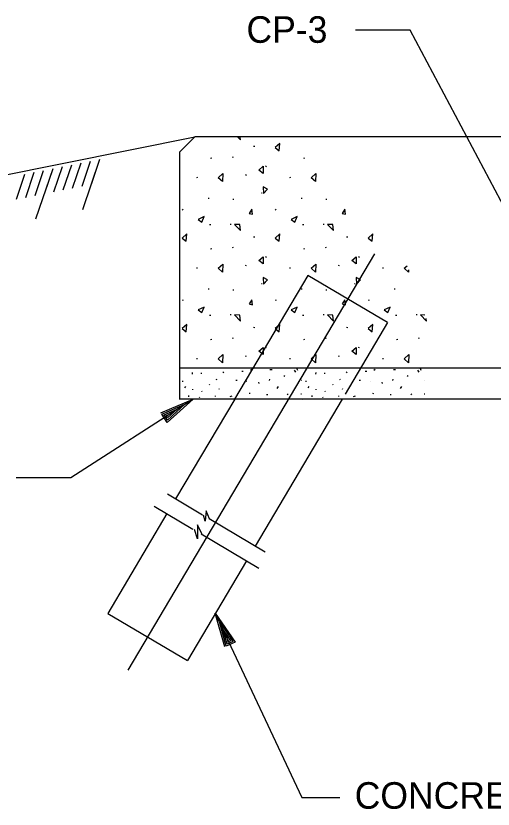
# Model space of a CAD drawing. Extents: x 44742.55 to 44745.38, y 44738.95 to 44741.13.
# Drawn here: x 44742.882 to 44743.044, y 44740.239 to 44740.5083 of the extents above; entities that cross this region are included whole.
import ezdxf

# ---------------------------------------------------------------- set-up
doc = ezdxf.new("R2010")
doc.units = 0
for name, color, linetype in [('G-ANNO-PATT', 7, 'Continuous'), ('Level 1', 7, 'Continuous'), ('Level 10', 7, 'Continuous'), ('Level 2', 7, 'Continuous'), ('Level 3', 7, 'Continuous'), ('Level 4', 7, 'Continuous'), ('S-ANNO-DIMS', 7, 'Continuous')]:
    doc.layers.add(name, color=color, linetype=linetype)

msp = doc.modelspace()

# ---------------------------------------------------------------- linework, layer by layer
at = {"layer": 'G-ANNO-PATT'}
for p, q in [((44742.96305, 44740.46391), (44742.96264, 44740.46398)), ((44742.94843, 44740.45995), (44742.94801, 44740.45984)), ((44742.95571, 44740.46037), (44742.95541, 44740.46026)), ((44742.97999, 44740.45995), (44742.97957, 44740.45984)), ((44742.96702, 44740.45706), (44742.96667, 44740.45727)), ((44742.94365, 44740.45341), (44742.94331, 44740.45337)), ((44742.96022, 44740.45416), (44742.95988, 44740.45431)), ((44742.97521, 44740.45341), (44742.97487, 44740.45337)), ((44742.96562, 44740.44809), (44742.96531, 44740.44811)), ((44742.9476, 44740.44626), (44742.94728, 44740.44631)), ((44742.956, 44740.44599), (44742.95558, 44740.44599)), ((44742.97916, 44740.44626), (44742.97885, 44740.44631)), ((44742.98756, 44740.44599), (44742.98714, 44740.44599)), ((44742.93875, 44740.44258), (44742.93838, 44740.44239)), ((44742.97031, 44740.44258), (44742.96994, 44740.44239)), ((44742.9481, 44740.43739), (44742.94767, 44740.43739)), ((44742.9551, 44740.43754), (44742.9547, 44740.43754)), ((44742.97966, 44740.43739), (44742.97924, 44740.43739)), ((44742.98666, 44740.43754), (44742.98626, 44740.43754)), ((44742.96305, 44740.43317), (44742.96264, 44740.43324)), ((44742.99461, 44740.43317), (44742.9942, 44740.43324)), ((44742.94843, 44740.42921), (44742.94801, 44740.42909)), ((44742.95571, 44740.42963), (44742.95541, 44740.42952)), ((44742.97999, 44740.42921), (44742.97957, 44740.42909)), ((44742.98727, 44740.42963), (44742.98697, 44740.42952)), ((44742.96702, 44740.42632), (44742.96667, 44740.42653)), ((44742.99859, 44740.42632), (44742.99824, 44740.42653)), ((44742.96022, 44740.42341), (44742.95988, 44740.42357)), ((44742.99178, 44740.42341), (44742.99145, 44740.42357)), ((44742.94365, 44740.42266), (44742.94331, 44740.42263)), ((44742.97521, 44740.42266), (44742.97487, 44740.42263)), ((44743.00677, 44740.42266), (44743.00643, 44740.42263)), ((44742.96562, 44740.41734), (44742.96531, 44740.41737)), ((44742.99718, 44740.41734), (44742.99687, 44740.41737)), ((44742.9476, 44740.41552), (44742.94728, 44740.41557)), ((44742.956, 44740.41525), (44742.95558, 44740.41525)), ((44742.97916, 44740.41552), (44742.97885, 44740.41557)), ((44742.98756, 44740.41525), (44742.98714, 44740.41525)), ((44743.01072, 44740.41552), (44743.01041, 44740.41557)), ((44742.93875, 44740.41184), (44742.93838, 44740.41165)), ((44742.97031, 44740.41184), (44742.96994, 44740.41165)), ((44743.00188, 44740.41184), (44743.0015, 44740.41165)), ((44742.9481, 44740.40665), (44742.94767, 44740.40665)), ((44742.9551, 44740.4068), (44742.9547, 44740.4068)), ((44742.97966, 44740.40665), (44742.97924, 44740.40665)), ((44742.98666, 44740.4068), (44742.98626, 44740.4068)), ((44743.01122, 44740.40665), (44743.0108, 44740.40665)), ((44743.01822, 44740.4068), (44743.01782, 44740.4068)), ((44742.96305, 44740.40243), (44742.96264, 44740.4025)), ((44742.99461, 44740.40243), (44742.9942, 44740.4025)), ((44742.94843, 44740.39847), (44742.94801, 44740.39835)), ((44742.95571, 44740.39889), (44742.95541, 44740.39877)), ((44742.97999, 44740.39847), (44742.97957, 44740.39835)), ((44742.98727, 44740.39889), (44742.98697, 44740.39877)), ((44743.01156, 44740.39847), (44743.01113, 44740.39835)), ((44743.01884, 44740.39889), (44743.01853, 44740.39877)), ((44742.96702, 44740.39558), (44742.96667, 44740.39579)), ((44742.99859, 44740.39558), (44742.99824, 44740.39579)), ((44742.94365, 44740.39192), (44742.94331, 44740.39189)), ((44742.96022, 44740.39267), (44742.95988, 44740.39283)), ((44742.97521, 44740.39192), (44742.97487, 44740.39189)), ((44742.99178, 44740.39267), (44742.99145, 44740.39283)), ((44743.00677, 44740.39192), (44743.00643, 44740.39189)), ((44742.96159, 44740.38803), (44742.96202, 44740.38837)), ((44742.96822, 44740.3883), (44742.96891, 44740.38831)), ((44742.97702, 44740.38731), (44742.97651, 44740.38805)), ((44742.97725, 44740.38871), (44742.97756, 44740.38803)), ((44743.00345, 44740.38803), (44743.00389, 44740.38837)), ((44743.0101, 44740.3883), (44743.01078, 44740.38831)), ((44742.94185, 44740.3872), (44742.94177, 44740.38671)), ((44742.94501, 44740.38674), (44742.94497, 44740.38718)), ((44742.95001, 44740.3849), (44742.95032, 44740.38499)), ((44742.95252, 44740.38711), (44742.95224, 44740.38752)), ((44742.95917, 44740.38756), (44742.95864, 44740.38764)), ((44742.96803, 44740.38499), (44742.96793, 44740.38449)), ((44742.97299, 44740.38587), (44742.97325, 44740.3862)), ((44742.98373, 44740.3872), (44742.98363, 44740.38671)), ((44742.98688, 44740.38674), (44742.98684, 44740.38718)), ((44742.99188, 44740.3849), (44742.9922, 44740.38499)), ((44742.9944, 44740.38711), (44742.99411, 44740.38752)), ((44743.00104, 44740.38756), (44743.00052, 44740.38764)), ((44743.00991, 44740.38499), (44743.00981, 44740.38449)), ((44743.01486, 44740.38587), (44743.01513, 44740.3862)), ((44742.93867, 44740.38405), (44742.93864, 44740.38446)), ((44742.93931, 44740.38202), (44742.93963, 44740.38251)), ((44742.9478, 44740.38293), (44742.9477, 44740.38315)), ((44742.95665, 44740.38462), (44742.95704, 44740.38462)), ((44742.96039, 44740.38415), (44742.96029, 44740.38423)), ((44742.96454, 44740.38352), (44742.96441, 44740.38396)), ((44742.97066, 44740.38187), (44742.97112, 44740.38247)), ((44742.97885, 44740.38465), (44742.97889, 44740.3846)), ((44742.98054, 44740.38405), (44742.98052, 44740.38446)), ((44742.98117, 44740.38202), (44742.9815, 44740.38251)), ((44742.98967, 44740.38293), (44742.98958, 44740.38315)), ((44742.99852, 44740.38462), (44742.99892, 44740.38462)), ((44743.00227, 44740.38415), (44743.00217, 44740.38423)), ((44743.00642, 44740.38352), (44743.00628, 44740.38396)), ((44743.01253, 44740.38187), (44743.01299, 44740.38247)), ((44743.02073, 44740.38465), (44743.02077, 44740.3846)), ((44742.94198, 44740.38137), (44742.94201, 44740.38155)), ((44742.94515, 44740.38063), (44742.9451, 44740.38096)), ((44742.95098, 44740.38157), (44742.95106, 44740.38179)), ((44742.9614, 44740.37998), (44742.96142, 44740.38038)), ((44742.96709, 44740.37973), (44742.9675, 44740.37974)), ((44742.9741, 44740.37963), (44742.97443, 44740.38002)), ((44742.97888, 44740.37988), (44742.97869, 44740.37984)), ((44742.98385, 44740.38137), (44742.98388, 44740.38155)), ((44742.98702, 44740.38063), (44742.98698, 44740.38096)), ((44742.99285, 44740.38157), (44742.99293, 44740.38179)), ((44743.00327, 44740.37998), (44743.0033, 44740.38038)), ((44743.00896, 44740.37973), (44743.00938, 44740.37974)), ((44743.01597, 44740.37963), (44743.01631, 44740.38002)), ((44743.02076, 44740.37988), (44743.02056, 44740.37984)), ((44742.93755, 44740.37824), (44742.93796, 44740.37827)), ((44742.94069, 44740.37902), (44742.94068, 44740.37948)), ((44742.94438, 44740.37862), (44742.9443, 44740.37886)), ((44742.94975, 44740.37914), (44742.94973, 44740.37936)), ((44742.95474, 44740.3791), (44742.95538, 44740.37933)), ((44742.97942, 44740.37824), (44742.97984, 44740.37827)), ((44742.98256, 44740.37902), (44742.98256, 44740.37948)), ((44742.98626, 44740.37862), (44742.98617, 44740.37886)), ((44742.99163, 44740.37914), (44742.9916, 44740.37936)), ((44742.9966, 44740.3791), (44742.99726, 44740.37933))]:
    msp.add_line(p, q, dxfattribs=at)
for points in [[(44742.95726, 44740.46714), (44742.95818, 44740.4662), (44742.95811, 44740.46714)], [(44743.01522, 44740.42129), (44743.01377, 44740.42262), (44743.01473, 44740.42348)], [(44743.01527, 44740.42205), (44743.01522, 44740.42129)], [(44743.02081, 44740.40671), (44743.01927, 44740.4068), (44743.02131, 44740.40472), (44743.02124, 44740.40555)]]:
    msp.add_lwpolyline(points, dxfattribs=at)
for points in [[(44742.97158, 44740.46504), (44742.96998, 44740.46364), (44742.97131, 44740.46252)], [(44742.96592, 44740.45485), (44742.96442, 44740.45598), (44742.96585, 44740.45726)], [(44742.9521, 44740.45203), (44742.95065, 44740.45337), (44742.95225, 44740.4548)], [(44742.98366, 44740.45203), (44742.98221, 44740.45337), (44742.98381, 44740.4548)], [(44742.96607, 44740.44798), (44742.96741, 44740.44948), (44742.96592, 44740.45027)], [(44742.96231, 44740.44099), (44742.9621, 44740.4427), (44742.96113, 44740.44127)], [(44742.99388, 44740.44099), (44742.99366, 44740.4427), (44742.9927, 44740.44127)], [(44742.94514, 44740.4383), (44742.94588, 44740.44022), (44742.94381, 44740.43921)], [(44742.9767, 44740.4383), (44742.97745, 44740.44022), (44742.97538, 44740.43921)], [(44742.95802, 44740.43744), (44742.95615, 44740.43754), (44742.95818, 44740.43546)], [(44742.98959, 44740.43744), (44742.98771, 44740.43754), (44742.98974, 44740.43546)], [(44742.94002, 44740.4343), (44742.93842, 44740.4329), (44742.93974, 44740.43178)], [(44742.97158, 44740.4343), (44742.96998, 44740.4329), (44742.97131, 44740.43178)], [(44743.00314, 44740.4343), (44743.00154, 44740.4329), (44743.00287, 44740.43178)], [(44742.96592, 44740.42411), (44742.96442, 44740.42524), (44742.96585, 44740.42652)], [(44742.99748, 44740.42411), (44742.99598, 44740.42524), (44742.99742, 44740.42652)], [(44742.9521, 44740.42129), (44742.95065, 44740.42262), (44742.95225, 44740.42405)], [(44742.98366, 44740.42129), (44742.98221, 44740.42262), (44742.98381, 44740.42405)], [(44742.96607, 44740.41723), (44742.96741, 44740.41873), (44742.96592, 44740.41953)], [(44742.99763, 44740.41723), (44742.99897, 44740.41873), (44742.99748, 44740.41953)], [(44742.96231, 44740.41025), (44742.9621, 44740.41196), (44742.96113, 44740.41053)], [(44742.99388, 44740.41025), (44742.99366, 44740.41196), (44742.9927, 44740.41053)], [(44742.94514, 44740.40756), (44742.94588, 44740.40948), (44742.94381, 44740.40847)], [(44742.9767, 44740.40756), (44742.97745, 44740.40948), (44742.97538, 44740.40847)], [(44743.00827, 44740.40756), (44743.00901, 44740.40948), (44743.00694, 44740.40847)], [(44742.95802, 44740.40669), (44742.95615, 44740.4068), (44742.95818, 44740.40472)], [(44742.98959, 44740.40669), (44742.98771, 44740.4068), (44742.98974, 44740.40472)], [(44742.94002, 44740.40355), (44742.93842, 44740.40216), (44742.93974, 44740.40104)], [(44742.97158, 44740.40355), (44742.96998, 44740.40216), (44742.97131, 44740.40104)], [(44743.00314, 44740.40355), (44743.00154, 44740.40216), (44743.00287, 44740.40104)], [(44742.96592, 44740.39337), (44742.96442, 44740.3945), (44742.96585, 44740.39577)], [(44742.99748, 44740.39337), (44742.99598, 44740.3945), (44742.99742, 44740.39577)], [(44742.9521, 44740.39055), (44742.95065, 44740.39188), (44742.95225, 44740.39331)], [(44742.98366, 44740.39055), (44742.98221, 44740.39188), (44742.98381, 44740.39331)], [(44743.01522, 44740.39055), (44743.01377, 44740.39188), (44743.01538, 44740.39331)]]:
    msp.add_lwpolyline(points, close=True, dxfattribs=at)
at = {"layer": 'Level 1'}
for p, q in [((44742.89807, 44740.44923), (44742.90096, 44740.45777)), ((44742.90125, 44740.44986), (44742.90414, 44740.45841)), ((44742.90444, 44740.4505), (44742.90733, 44740.45904)), ((44742.90473, 44740.44259), (44742.91052, 44740.45968)), ((44742.90763, 44740.45113), (44742.91052, 44740.45968)), ((44742.88532, 44740.44668), (44742.88821, 44740.45522)), ((44742.88851, 44740.44731), (44742.8914, 44740.45586)), ((44742.8888, 44740.43941), (44742.89459, 44740.45649)), ((44742.8917, 44740.44795), (44742.89459, 44740.45649)), ((44742.89488, 44740.44859), (44742.89777, 44740.45713)), ((44742.88214, 44740.44604), (44742.88503, 44740.45459)), ((44743.00368, 44740.42755), (44742.91999, 44740.28619)), ((44743.01888, 44740.38731), (44743.01838, 44740.38805)), ((44743.01914, 44740.38871), (44743.01942, 44740.38803)), ((44742.94533, 44740.33887), (44742.93342, 44740.34593)), ((44742.92892, 44740.34191), (44742.94206, 44740.33412)), ((44742.94661, 44740.34033), (44742.9462, 44740.33681)), ((44742.94769, 44740.33755), (44742.94661, 44740.34033)), ((44742.9462, 44740.33681), (44742.9456, 44740.33881)), ((44742.9666, 44740.32629), (44742.94763, 44740.33752)), ((44742.94363, 44740.33073), (44742.94262, 44740.33391)), ((44742.94365, 44740.3355), (44742.94363, 44740.33073)), ((44742.94507, 44740.33244), (44742.94365, 44740.3355)), ((44742.94488, 44740.33245), (44742.96445, 44740.32087)), ((44742.94967, 44740.30551), (44742.94967, 44740.30551)), ((44742.95106, 44740.30256), (44742.95106, 44740.30256))]:
    msp.add_line(p, q, dxfattribs=at)
at = {"layer": 'Level 10'}
for p, q in [((44742.93755, 44740.46201), (44742.94276, 44740.46722)), ((44743.09457, 44740.46722), (44742.94276, 44740.46722)), ((44742.93755, 44740.46201), (44742.93755, 44740.37824)), ((44743.06913, 44740.38871), (44742.93755, 44740.38871)), ((44743.06913, 44740.37824), (44742.93755, 44740.37824))]:
    msp.add_line(p, q, dxfattribs=at)
at = {"layer": 'Level 2'}
for p, q in [((44742.9811, 44740.42023), (44742.95623, 44740.37824)), ((44743.00813, 44740.40423), (44742.9811, 44740.42023)), ((44743.00813, 44740.40423), (44742.99371, 44740.3799)), ((44742.95624, 44740.37824), (44742.93615, 44740.34431)), ((44742.9927, 44740.37817), (44742.96317, 44740.32831)), ((44742.93322, 44740.33937), (44742.91314, 44740.30545)), ((44742.96024, 44740.32337), (44742.94017, 44740.28945)), ((44742.91314, 44740.30545), (44742.94017, 44740.28945))]:
    msp.add_line(p, q, dxfattribs=at)
at = {"layer": 'Level 3'}
msp.add_line((44742.82231, 44740.44315), (44742.94276, 44740.46722), dxfattribs=at)
at = {"layer": 'S-ANNO-DIMS'}
for p, q in [((44742.9421, 44740.37824), (44742.9421, 44740.37824)), ((44742.93936, 44740.37648), (44742.93936, 44740.37648))]:
    msp.add_line(p, q, dxfattribs=at)
for points in [[(44743.06199, 44740.41652), (44743.0158, 44740.50341), (44742.99727, 44740.50341)], [(44742.9421, 44740.37824), (44742.90063, 44740.35153), (44742.8821, 44740.35153)], [(44742.93122, 44740.37354), (44742.9421, 44740.37824), (44742.93332, 44740.37028), (44742.93152, 44740.37307), (44742.93936, 44740.37648), (44742.9334, 44740.37108), (44742.93225, 44740.37287), (44742.93674, 44740.37479), (44742.93349, 44740.37187), (44742.93301, 44740.37261), (44742.934, 44740.37303)], [(44742.94967, 44740.30551), (44742.97901, 44740.24295), (44742.99197, 44740.24295)], [(44742.95288, 44740.2941), (44742.94967, 44740.30551), (44742.95639, 44740.29575), (44742.95339, 44740.29434), (44742.95106, 44740.30256), (44742.95561, 44740.29594), (44742.95369, 44740.29503), (44742.95238, 44740.29973), (44742.95484, 44740.29612), (44742.95404, 44740.29575), (44742.95376, 44740.2968)]]:
    msp.add_lwpolyline(points, dxfattribs=at)

# ---------------------------------------------------------------- texts
at = {"layer": 'Level 4'}
for s, height, p in [('CP-3', 0.00902, (44742.96024, 44740.49916)), ('CONCRETE PILING', 0.0090203, (44742.99697, 44740.23916))]:
    msp.add_text(s, height=height, dxfattribs=at).set_placement(p)

doc.saveas('drawing.dxf')
